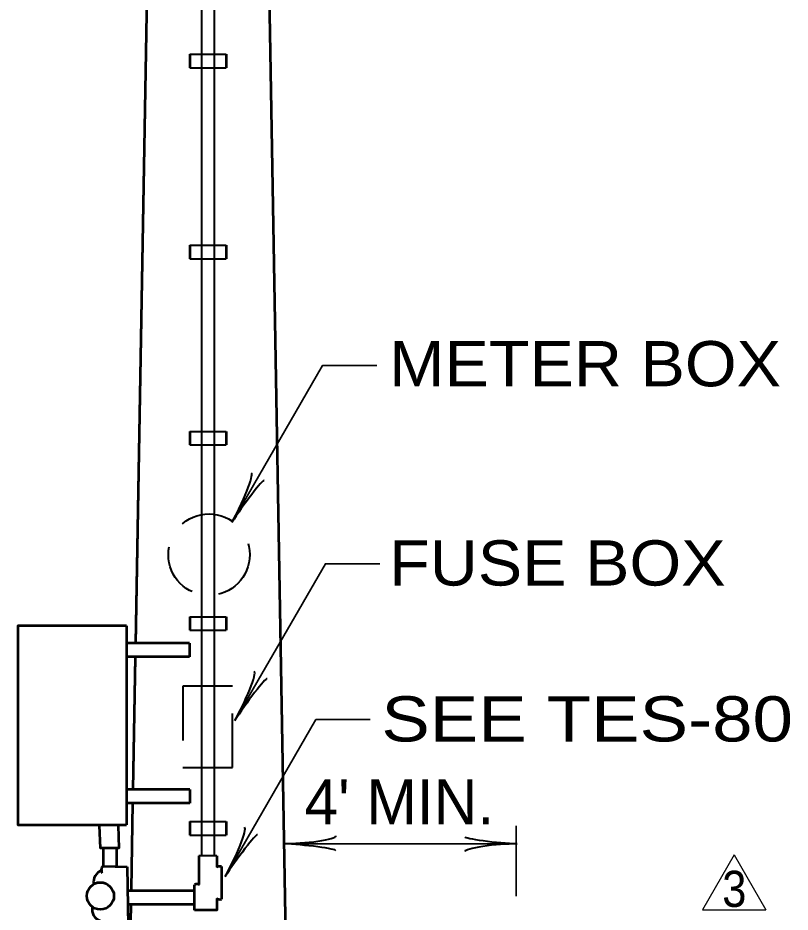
# Model space of a CAD drawing. Extents: x 12366 to 13046, y 9129 to 9570.
# Drawn here: x 12454.35 to 12497.02, y 9412.3 to 9461.74 of the extents above; entities that cross this region are included whole.
import ezdxf
from ezdxf.enums import TextEntityAlignment as Align

# ---------------------------------------------------------------- set-up
doc = ezdxf.new("R2010")
doc.units = 0
doc.linetypes.add('MEDIUM_DASHED', pattern=[4.5, 3, -1.5])
doc.layers.add('1', color=7, linetype='Continuous', lineweight=53)

msp = doc.modelspace()

# ---------------------------------------------------------------- linework, layer by layer
at = {"layer": '1'}
for p, q in [((12462.852, 9542.164), (12460.844, 9427.165)), ((12462.852, 9542.164), (12460.844, 9427.137)), ((12462.852, 9542.164), (12460.844, 9427.133)), ((12467.018, 9532.655), (12469.434, 9394.187)), ((12467.018, 9532.655), (12469.382, 9397.186)), ((12467.018, 9532.655), (12469.382, 9397.186)), ((12463.852, 9459.728), (12463.852, 9458.978)), ((12465.852, 9459.728), (12465.852, 9458.978)), ((12463.852, 9449.164), (12463.852, 9448.414)), ((12465.852, 9449.164), (12465.852, 9448.414)), ((12463.852, 9438.879), (12463.852, 9438.129)), ((12465.852, 9438.879), (12465.852, 9438.129)), ((12463.852, 9428.633), (12463.852, 9427.883)), ((12465.852, 9428.633), (12465.852, 9427.883)), ((12460.352, 9428.133), (12460.352, 9417.133)), ((12463.841, 9427.165), (12460.341, 9427.165)), ((12463.841, 9427.165), (12463.841, 9426.415)), ((12463.841, 9426.415), (12460.341, 9426.415)), ((12460.831, 9426.415), (12460.703, 9419.079)), ((12460.831, 9426.383), (12460.703, 9419.077)), ((12460.831, 9426.381), (12460.703, 9419.077)), ((12463.852, 9419.077), (12460.352, 9419.077)), ((12463.852, 9419.077), (12463.852, 9418.327)), ((12463.852, 9418.327), (12460.352, 9418.327)), ((12460.69, 9418.327), (12460.607, 9413.563)), ((12460.69, 9418.327), (12460.607, 9413.563)), ((12463.852, 9417.306), (12463.852, 9416.556)), ((12465.852, 9417.306), (12465.852, 9416.556)), ((12459.059, 9415.833), (12459.059, 9414.833)), ((12459.809, 9415.833), (12459.809, 9414.833)), ((12464.354, 9415.413), (12464.354, 9413.824)), ((12465.354, 9415.413), (12465.354, 9414.779)), ((12459.059, 9414.833), (12460.392, 9414.798)), ((12460.392, 9414.798), (12460.449, 9411.546)), ((12465.604, 9414.813), (12465.604, 9413.013)), ((12464.104, 9412.413), (12464.104, 9413.813)), ((12464.078, 9413.477), (12460.415, 9413.477)), ((12464.078, 9412.727), (12460.428, 9412.727)), ((12460.591, 9412.658), (12460.532, 9409.301)), ((12460.591, 9412.652), (12460.532, 9409.299)), ((12460.591, 9412.652), (12460.532, 9409.288))]:
    msp.add_line(p, q, dxfattribs=at)
at = {"layer": '1', "lineweight": 40}
for p, q in [((12464.502, 9501.414), (12464.502, 9415.414)), ((12465.202, 9501.414), (12465.202, 9415.414)), ((12463.852, 9459.728), (12465.852, 9459.728)), ((12463.852, 9458.978), (12465.852, 9458.978)), ((12463.852, 9449.164), (12465.852, 9449.164)), ((12463.852, 9448.414), (12465.852, 9448.414)), ((12463.852, 9438.879), (12465.852, 9438.879)), ((12463.852, 9438.129), (12465.852, 9438.129)), ((12463.852, 9428.633), (12465.852, 9428.633)), ((12463.852, 9427.883), (12465.852, 9427.883)), ((12463.852, 9417.306), (12465.852, 9417.306)), ((12463.852, 9416.556), (12465.852, 9416.556)), ((12465.354, 9415.413), (12464.354, 9415.413))]:
    msp.add_line(p, q, dxfattribs=at)
at = {"layer": '1', "lineweight": 35}
for p, q in [((12481.882, 9413.184), (12481.882, 9417.078)), ((12481.932, 9416.078), (12469.049, 9416.078))]:
    msp.add_line(p, q, dxfattribs=at)
at = {"layer": '1', "lineweight": 25}
for p, q in [((12493.927, 9415.463), (12492.177, 9412.432)), ((12493.927, 9415.463), (12495.677, 9412.432)), ((12492.177, 9412.432), (12495.677, 9412.432))]:
    msp.add_line(p, q, dxfattribs=at)
at = {"layer": '1', "lineweight": 35}
for points in [[(12466.188, 9433.864), (12471.188, 9442.525), (12474.188, 9442.525)], [(12466.348, 9422.901), (12471.348, 9431.561), (12474.348, 9431.561)], [(12465.816, 9414.28), (12470.816, 9422.94), (12473.816, 9422.94)]]:
    msp.add_lwpolyline(points, dxfattribs=at)
at = {"layer": '1'}
for points in [[(12460.352, 9428.133), (12454.352, 9428.133), (12454.352, 9417.133), (12460.352, 9417.133)], [(12459.902, 9417.083), (12459.923, 9415.834), (12458.923, 9415.834), (12458.858, 9417.082)], [(12465.354, 9413.047), (12465.354, 9412.413), (12464.104, 9412.413)]]:
    msp.add_lwpolyline(points, dxfattribs=at)
at = {"layer": '1', "linetype": 'MEDIUM_DASHED', "lineweight": 40}
msp.add_lwpolyline([(12463.457, 9424.788), (12463.457, 9420.288), (12466.207, 9420.288), (12466.207, 9424.788)], close=True, dxfattribs=at)
msp.add_circle((12464.916, 9432.061), 2.25, dxfattribs=at)
at = {"layer": '1'}
msp.add_circle((12458.91, 9413.192), 0.75, dxfattribs=at)
for centre, radius, start, end in [((12465.525, 9414.455), 0.367, 77.5348, 124.3927), ((12459.185, 9413.979), 0.652, 108.3808, 191.4061), ((12464.244, 9413.474), 0.367, 65.6073, 112.4652), ((12465.526, 9413.37), 0.367, 235.6073, 282.4652), ((12459.101, 9412.439), 0.652, 168.5939, 251.6192)]:
    msp.add_arc(centre, radius, start, end, dxfattribs=at)
at = {"layer": '1', "lineweight": 40}
for centre, major_axis, ratio, start_param, end_param in [((12466.494, 9434.947), (-0.758, -1.625), 0.122415, 0.896353, 3.141593), ((12466.932, 9434.729), (1.03, 1.433), 0.07063, 6.282307, 8.559703), ((12466.654, 9423.984), (-0.758, -1.625), 0.122415, 0.896353, 3.141593), ((12467.091, 9423.766), (1.03, 1.433), 0.07063, 6.282307, 8.559703), ((12466.122, 9415.363), (-0.758, -1.625), 0.122415, 0.896353, 3.141593), ((12466.559, 9415.144), (1.03, 1.433), 0.07063, 6.282307, 8.559703), ((12470.141, 9416.355), (-1.786, -0.156), 0.122415, 0.896353, 3.141593), ((12470.141, 9416.355), (-1.786, -0.156), 0.122415, 0.896353, 3.141593), ((12480.812, 9416.29), (1.756, -0.176), 0.07063, 3.140715, 5.41811), ((12470.17, 9415.867), (-1.756, 0.176), 0.07063, 3.140715, 5.41811), ((12470.17, 9415.867), (-1.756, 0.176), 0.07063, 3.140715, 5.41811), ((12480.841, 9415.802), (1.786, 0.156), 0.122415, 0.896353, 3.141593)]:
    msp.add_ellipse(centre, major_axis=major_axis, ratio=ratio, start_param=start_param, end_param=end_param, dxfattribs=at)
at = {"layer": '1'}
msp.add_ellipse((12459.102, 9414.586), major_axis=(-0.042, 0.247), ratio=0.545945, start_param=6.282989, end_param=8.321681, dxfattribs=at)

# ---------------------------------------------------------------- texts
for s, height, width, p in [('METER BOX', 2.5, 1.1, (12474.863, 9441.369)), ('FUSE BOX', 2.5, 1.1, (12474.863, 9430.353)), ('SEE TES-80', 2.5, 1.2, (12474.437, 9421.731)), ('3', 2, 0.9, (12493.27, 9412.584))]:
    msp.add_text(s, height=height, dxfattribs=dict(at, width=width)).set_placement(p)
msp.add_text("4' MIN.", height=2.5, dxfattribs=at).set_placement((12475.429, 9417.146), align=Align.CENTER)

doc.saveas('drawing.dxf')
